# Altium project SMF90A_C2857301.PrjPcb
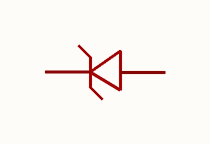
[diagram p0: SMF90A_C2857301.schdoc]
1 sheet, 1 parts. Net scope: global (net labels, ports and power ports of the same name join across sheets).

## Sheet SMF90A_C2857301.schdoc
size 127 x 101 mm

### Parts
D?  smf90a_c2857301  [SOD-123FL_L2.8-W1.8-LS3.6-RD]  (value not drawn)

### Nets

Not connected (* = marked no-connect by the designer): D? 1 2

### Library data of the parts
D? = smf90a_c2857301: 极性:单向;反向截止电压(Vrwm):90V;钳位电压:146V;峰值脉冲电流(Ipp):1.4A;峰值脉冲功率(Ppp):200W@10/1000us;击穿电压(VBR):100V;; Manufacturer: JSMSEMI(杰盛微); ManufacturerPart: SMF90A; AddInBom: yes; ModelId: 9a6bf0a398604d2998ad78800a7c8ef9; ModelTransform: 141.732,70.866,0,0,0,0,0,0,0; Polarity: 单向; Reverse Stand-Off Voltage (Vrwm): 90V; Clamping Voltage: 146V; Peak Pulse Current (Ipp): 1.4A; Voltage - Breakdown: 100V; Reverse Leakage Current (Ir): 1uA; Number of Channels: 单路; Type: TVS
